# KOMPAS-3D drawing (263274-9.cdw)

Referenced files in /: h7
Referenced files: вал титоходный.cdw
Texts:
  Вал тихоходный
  Loner-XP
  WolfishLair
  Текст на чертеже
  Размерные надписи
  Шероховатость
  Линия-выноска #1
  Линия-выноска #2
  Линия-выноска #3
  Отклонения формы и база
  Заголовок таблицы
  Ячейка таблицы
  Стрелка вида
  Обозначение изменения
  Фигурная скобка
  Номер узла
  Марка координационной оси
  VRCb
  Выносная надпись
  Обозначение узла
  Марка/позиционное обозначение с линией-выноской
  Марка/позиционное обозначение на линии
  Марка/позиционное обозначение без линии-выноски
  Ra 3.2
  Ra 0.8
  JS7
  Стандартные изделия
  Шпонка 14x9x36 ГОСТ 23360-78
  Шпонка 14x12x36 ГОСТ 10748-79
  Месечко А.В
  Овчаренко В.В.
  Сталь 45 ГОСТ 543 - 71
  ВНУ им. Даля
  гр. МЗ - 06в
Dimensions and other numbers on the sheet: 701.48.00.002; 7; 38; 46; 20; 106; 50; 29; 282; 43; 45; 0.003; 0.004; 10; 14; 32; 4; 0.02; 0.08; 48; 42,5; 1:1; 1; 701.13.00.002-; 0; 2; 3; 5; 6; 8; 9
